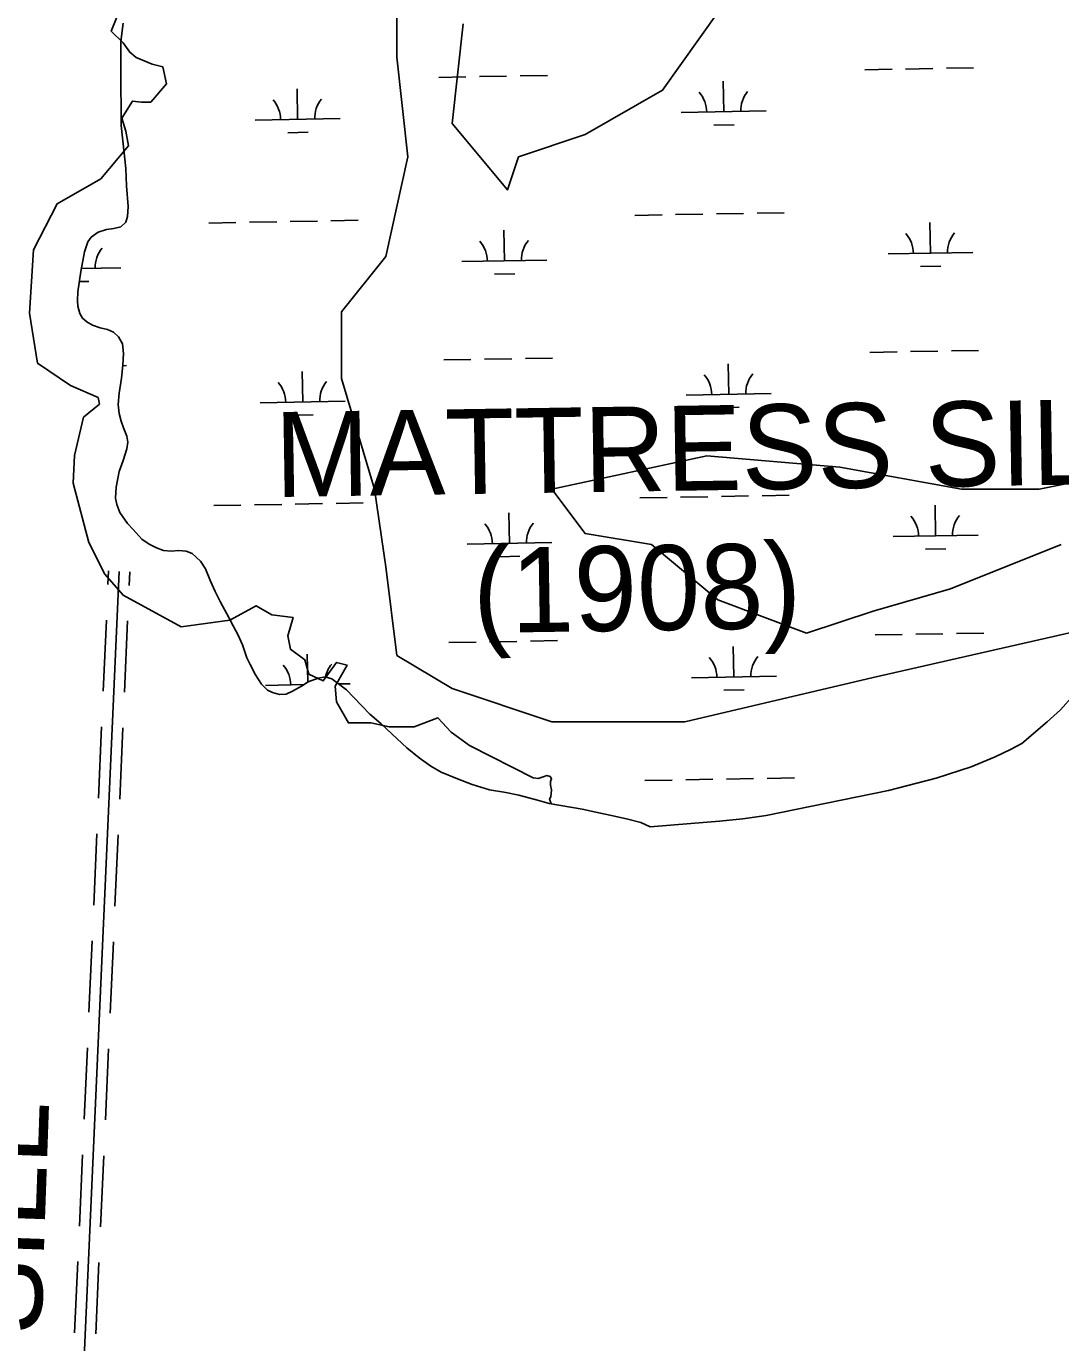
# Model space of a CAD drawing. Extents: x 3914892 to 3953151, y 242587 to 268572.
# Drawn here: x 3942954 to 3944172, y 257887 to 259437 of the extents above; entities that cross this region are included whole.
import ezdxf

# ---------------------------------------------------------------- set-up
doc = ezdxf.new("R2010")
doc.units = 0
for name, color, linetype in [('V-RIVR-EDGE', 7, 'Continuous'), ('V-RRAP-DIKE', 7, 'Continuous'), ('V-RRAP-SILL-IDEN', 7, 'Continuous'), ('V-SITE-VEGE', 7, 'Continuous'), ('V-TOPO-SHOR', 7, 'Continuous'), ('V-WETL-SWMP', 7, 'Continuous')]:
    doc.layers.add(name, color=color, linetype=linetype)

msp = doc.modelspace()

# ---------------------------------------------------------------- linework, layer by layer
at = {"layer": 'V-RIVR-EDGE'}
for points in [[(3943066.6, 259461.9), (3943054.2, 259430.8), (3943068.1, 259416.9), (3943075.9, 259406), (3943083.6, 259399.8), (3943102.3, 259392.1), (3943114.7, 259389), (3943119.3, 259368.8), (3943100.7, 259347.1), (3943089.8, 259347.1), (3943079, 259348.6), (3943066.6, 259328.5), (3943071.2, 259313), (3943074.3, 259295.9), (3943041.8, 259257.1), (3942990.6, 259227.6), (3942962.7, 259173.3), (3942958, 259098.9), (3942967.3, 259039.9), (3943006.1, 259013.6), (3943038.7, 258999.6), (3943040.2, 258991.9), (3943021.6, 258976.3), (3943010.7, 258931.4), (3943009.2, 258898.8), (3943027.8, 258829), (3943046.4, 258791.8), (3943068.1, 258766.9), (3943136.4, 258729.7), (3943193.8, 258737.5), (3943224.8, 258754.5), (3943243.4, 258743.7), (3943268.2, 258740.6), (3943262, 258718.9), (3943265.1, 258703.3), (3943282.2, 258690.9), (3943286.8, 258673.9), (3943303.9, 258666.1), (3943319.4, 258687.8), (3943331.8, 258684.7), (3943317.9, 258659.9), (3943319.4, 258641.3), (3943333.4, 258616.5), (3943359.8, 258616.5), (3943381.5, 258611.8), (3943410.9, 258611.8), (3943438.9, 258622.7), (3943454.4, 258605.6), (3943476.1, 258590.1), (3943551.7, 258551.5)], [(3943551.4, 258551.8), (3943557.1, 258551.1), (3943562.9, 258553.3), (3943567, 258554.5), (3943571, 258553.6), (3943572.8, 258550.8), (3943571.3, 258547.6), (3943571.6, 258543.3), (3943572.6, 258538), (3943572, 258529.4), (3943570.4, 258527.1), (3943572.2, 258521.5)]]:
    msp.add_lwpolyline(points, dxfattribs=at)
at = {"layer": 'V-RRAP-DIKE'}
for points in [[(3942986.1, 257058.8), (3943063.5, 258794.9)], [(3943050.3, 258779.7), (3943051, 258795.4)], [(3943075.3, 258778.5), (3943076, 258794.3)], [(3943044.7, 258653.8), (3943048.4, 258737.7)], [(3943069.7, 258652.7), (3943073.4, 258736.6)], [(3943039.1, 258527.9), (3943042.8, 258611.8)], [(3943064.1, 258526.8), (3943067.8, 258610.7)], [(3943033.5, 258402), (3943037.2, 258486)], [(3943058.4, 258400.9), (3943062.2, 258484.8)], [(3943027.8, 258276.2), (3943031.6, 258360.1)], [(3943052.8, 258275), (3943056.6, 258359)], [(3943022.2, 258150.3), (3943026, 258234.2)], [(3943047.2, 258149.2), (3943051, 258233.1)], [(3943016.6, 258024.4), (3943020.4, 258108.3)], [(3943041.6, 258023.3), (3943045.3, 258107.2)], [(3943011, 257898.5), (3943014.7, 257982.5)], [(3943036, 257897.4), (3943039.7, 257981.3)]]:
    msp.add_lwpolyline(points, dxfattribs=at)
at = {"layer": 'V-SITE-VEGE'}
for points in [[(3943390.4, 259504.7), (3943390.4, 259400.4), (3943403.4, 259283), (3943377.4, 259165.6), (3943325.2, 259100.4), (3943325.2, 259022.1), (3943364.3, 258891.7), (3943377.4, 258800.4), (3943390.4, 258696.1), (3943455.6, 258656.9), (3943573, 258617.8), (3943729.5, 258617.8), (3943951.3, 258670), (3944238.2, 258735.2)], [(3943768.6, 259452.6), (3943703.4, 259361.3), (3943612.1, 259309.1), (3943533.9, 259283), (3943520.8, 259243.9), (3943455.6, 259322.1), (3943468.7, 259439.5)], [(3944173, 258826.5), (3944042.6, 258774.3), (3943951.3, 258748.2), (3943873, 258722.1), (3943768.6, 258761.3), (3943690.4, 258826.5), (3943612.1, 258839.5), (3943573, 258891.7), (3943755.6, 258930.8), (3943912.1, 258917.8), (3944055.6, 258891.7), (3944146.9, 258891.7), (3944277.3, 258917.8)]]:
    msp.add_lwpolyline(points, dxfattribs=at)
at = {"layer": 'V-TOPO-SHOR'}
msp.add_lwpolyline([(3943688.9, 258494.4), (3943736.6, 258498), (3943770.5, 258501), (3943797.9, 258503.7), (3943825.4, 258507.7), (3943859.8, 258514.7), (3943969.3, 258537.1), (3944025.8, 258551.4), (3944066.7, 258565), (3944095.1, 258576.8), (3944113, 258585.3), (3944126.5, 258592.5), (3944156.4, 258617.7), (3944171.9, 258631.9), (3944187.3, 258649.2)], dxfattribs=at)
at = {"layer": 'V-WETL-SWMP'}
for p, q in [((3943065.5, 259418.8), (3943068, 259440.2)), ((3943065.6, 259400.8), (3943065.5, 259418.8)), ((3943065.4, 259385.7), (3943065.6, 259400.8)), ((3944037.7, 259387.1), (3944069.7, 259387.7)), ((3943065.9, 259319.9), (3943065.4, 259385.7)), ((3943439.8, 259376.4), (3943471.8, 259377)), ((3943487.8, 259377.3), (3943519.8, 259377.8)), ((3943535.8, 259378.1), (3943567.8, 259378.7)), ((3943775.5, 259336), (3943774.8, 259372)), ((3943941.7, 259385.4), (3943973.7, 259385.9)), ((3943989.7, 259386.2), (3944021.7, 259386.8)), ((3943065.5, 259369.7), (3943066, 259369.7)), ((3943273.6, 259327), (3943273, 259363)), ((3943223.7, 259326.1), (3943323.6, 259327.9)), ((3943725.5, 259335.1), (3943825.5, 259336.9)), ((3943071.2, 259269), (3943065.9, 259319.9)), ((3943261.9, 259311.3), (3943285.9, 259311.8)), ((3943763.7, 259320.3), (3943787.7, 259320.7)), ((3943072.2, 259248.8), (3943071.2, 259269)), ((3943073.9, 259224.5), (3943072.2, 259248.8)), ((3943073.2, 259212.7), (3943073.9, 259224.5)), ((3943814.8, 259216.6), (3943846.8, 259217.1)), ((3943065.5, 259200.6), (3943071.2, 259206)), ((3943071.2, 259206), (3943073.2, 259212.7)), ((3943169, 259205), (3943201, 259205.6)), ((3943217, 259205.9), (3943249, 259206.4)), ((3943264.9, 259206.7), (3943296.9, 259207.3)), ((3943312.9, 259207.6), (3943344.9, 259208.2)), ((3943670.8, 259214), (3943702.8, 259214.6)), ((3943718.8, 259214.9), (3943750.8, 259215.4)), ((3943766.8, 259215.7), (3943798.8, 259216.3)), ((3944019, 259169.5), (3944018.3, 259205.5)), ((3943026.4, 259182.9), (3943030.5, 259188.4)), ((3943030.5, 259188.4), (3943038.8, 259194.3)), ((3943038.8, 259194.3), (3943048.7, 259197.3)), ((3943048.7, 259197.3), (3943057, 259198.4)), ((3943057, 259198.4), (3943065.5, 259200.6)), ((3943517.1, 259160.5), (3943516.5, 259196.5)), ((3943018.4, 259147.9), (3943022.8, 259171.2)), ((3943022.8, 259171.2), (3943026.4, 259182.9)), ((3943969, 259168.6), (3944069, 259170.4)), ((3943467.1, 259159.6), (3943567.1, 259161.4)), ((3943014.9, 259123.9), (3943018.4, 259147.9)), ((3943019.1, 259151.6), (3943065.3, 259152.4)), ((3943505.4, 259144.9), (3943529.4, 259145.3)), ((3944007.2, 259153.8), (3944031.2, 259154.3)), ((3943014.3, 259113.8), (3943014.9, 259123.9)), ((3943016.7, 259136.1), (3943027.6, 259136.3)), ((3943014.8, 259107.3), (3943014.3, 259113.8)), ((3943017, 259098.4), (3943014.8, 259107.3)), ((3943020.4, 259092.9), (3943017, 259098.4)), ((3943025.4, 259088.6), (3943020.4, 259092.9)), ((3943032.1, 259084.9), (3943025.4, 259088.6)), ((3943041.1, 259081.5), (3943032.1, 259084.9)), ((3943049.9, 259079.5), (3943041.1, 259081.5)), ((3943056.6, 259076.4), (3943049.9, 259079.5)), ((3943062.7, 259071.1), (3943056.6, 259076.4)), ((3943067.2, 259062.6), (3943062.7, 259071.1)), ((3943068.7, 259051.4), (3943067.2, 259062.6)), ((3943067.8, 259037.5), (3943068.7, 259051.4)), ((3943947.6, 259052.7), (3943979.6, 259053.3)), ((3943995.6, 259053.6), (3944027.6, 259054.2)), ((3944043.6, 259054.5), (3944075.6, 259055)), ((3943066.3, 259022.5), (3943067.8, 259037.5)), ((3943067.8, 259037), (3943072, 259037.1)), ((3943445.8, 259043.8), (3943477.8, 259044.3)), ((3943493.8, 259044.6), (3943525.8, 259045.2)), ((3943541.8, 259045.5), (3943573.8, 259046.1)), ((3943781.4, 259003.3), (3943780.8, 259039.3)), ((3943063.3, 259004.9), (3943066.3, 259022.5)), ((3943279.6, 258994.4), (3943278.9, 259030.4)), ((3943062.4, 258991.4), (3943063.3, 259004.9)), ((3943731.4, 259002.4), (3943831.4, 259004.2)), ((3943063.5, 258980.7), (3943062.4, 258991.4)), ((3943229.6, 258993.5), (3943329.6, 258995.3)), ((3943769.7, 258987.7), (3943793.7, 258988.1)), ((3943065.7, 258971.6), (3943063.5, 258980.7)), ((3943068.7, 258964.1), (3943065.7, 258971.6)), ((3943267.9, 258978.7), (3943291.9, 258979.1)), ((3943072.5, 258954.2), (3943068.7, 258964.1)), ((3943073.5, 258947), (3943072.5, 258954.2)), ((3943068.2, 258925.6), (3943072.3, 258939)), ((3943072.3, 258939), (3943073.5, 258947)), ((3943063.6, 258912.6), (3943068.2, 258925.6)), ((3943059.9, 258893.9), (3943063.6, 258912.6)), ((3943059.1, 258881.2), (3943059.9, 258893.9)), ((3943060.6, 258873.6), (3943059.1, 258881.2)), ((3943676.7, 258881.4), (3943708.7, 258881.9)), ((3943724.7, 258882.2), (3943756.7, 258882.8)), ((3943772.7, 258883.1), (3943804.7, 258883.7)), ((3943820.7, 258884), (3943852.7, 258884.5)), ((3943064.3, 258864.3), (3943060.6, 258873.6)), ((3943073.3, 258851.5), (3943064.3, 258864.3)), ((3943174.9, 258872.4), (3943206.9, 258873)), ((3943222.9, 258873.3), (3943254.9, 258873.8)), ((3943270.9, 258874.1), (3943302.9, 258874.7)), ((3943318.9, 258875), (3943350.9, 258875.5)), ((3943523.1, 258827.9), (3943522.4, 258863.9)), ((3944024.9, 258836.9), (3944024.3, 258872.8)), ((3943079.8, 258844.2), (3943073.3, 258851.5)), ((3943090.1, 258832.9), (3943079.8, 258844.2)), ((3943098.9, 258827.1), (3943090.1, 258832.9)), ((3943974.9, 258836), (3944074.9, 258837.7)), ((3943107.4, 258822.7), (3943098.9, 258827.1)), ((3943115.8, 258819.4), (3943107.4, 258822.7)), ((3943124.6, 258818.8), (3943115.8, 258819.4)), ((3943133.9, 258819.7), (3943124.6, 258818.8)), ((3943142.4, 258818.8), (3943133.9, 258819.7)), ((3943149.3, 258816.1), (3943142.4, 258818.8)), ((3943159.2, 258807.1), (3943149.3, 258816.1)), ((3943473.1, 258827), (3943573.1, 258828.8)), ((3944013.2, 258821.2), (3944037.2, 258821.6)), ((3943165.2, 258797.9), (3943159.2, 258807.1)), ((3943511.4, 258812.2), (3943535.4, 258812.7)), ((3943171.1, 258783.3), (3943165.2, 258797.9)), ((3943176.7, 258771.2), (3943171.1, 258783.3)), ((3943182.4, 258759.5), (3943176.7, 258771.2)), ((3943192.9, 258739.7), (3943182.4, 258759.5)), ((3943197.8, 258730.8), (3943192.9, 258739.7)), ((3943203.1, 258720.8), (3943197.8, 258730.8)), ((3943208.6, 258708.3), (3943203.1, 258720.8)), ((3944001.6, 258721), (3944033.6, 258721.6)), ((3944049.6, 258721.8), (3944081.6, 258722.4)), ((3943214, 258693.2), (3943208.6, 258708.3)), ((3943451.8, 258711.1), (3943483.7, 258711.7)), ((3943499.7, 258712), (3943531.7, 258712.6)), ((3943547.7, 258712.9), (3943579.7, 258713.4)), ((3943787.4, 258670.7), (3943786.7, 258706.7)), ((3943953.6, 258720.1), (3943985.6, 258720.7)), ((3943217.7, 258685.2), (3943214, 258693.2)), ((3943285.5, 258664.5), (3943284.9, 258697.7)), ((3943224, 258673.2), (3943217.7, 258685.2)), ((3943231.2, 258662), (3943224, 258673.2)), ((3943238, 258655.3), (3943231.2, 258662)), ((3943235.6, 258660.8), (3943280.9, 258661.7)), ((3943278, 258659.9), (3943267.7, 258653.8)), ((3943286.1, 258665), (3943278, 258659.9)), ((3943297.7, 258669.3), (3943286.1, 258665)), ((3943306.2, 258670.8), (3943297.7, 258669.3)), ((3943313.9, 258668.6), (3943306.2, 258670.8)), ((3943323.5, 258661.5), (3943313.9, 258668.6)), ((3943322.3, 258662.4), (3943335.5, 258662.6)), ((3943331, 258655.5), (3943323.5, 258661.5)), ((3943737.4, 258669.8), (3943837.4, 258671.6)), ((3943244.1, 258652.3), (3943238, 258655.3)), ((3943252.3, 258650), (3943244.1, 258652.3)), ((3943260.3, 258650.5), (3943252.3, 258650)), ((3943267.7, 258653.8), (3943260.3, 258650.5)), ((3943339.9, 258646.4), (3943331, 258655.5)), ((3943358.5, 258626.8), (3943339.9, 258646.4)), ((3943775.7, 258655.1), (3943799.6, 258655.5)), ((3944187.3, 258649.2), (3944171.9, 258631.9)), ((3944171.9, 258631.9), (3944156.4, 258617.7)), ((3943372.1, 258615.4), (3943358.5, 258626.8)), ((3943390.7, 258597.8), (3943372.1, 258615.4)), ((3944156.4, 258617.7), (3944126.5, 258592.5)), ((3943402.3, 258587.2), (3943390.7, 258597.8)), ((3943416.9, 258575.4), (3943402.3, 258587.2)), ((3944113, 258585.3), (3944095.1, 258576.8)), ((3944126.5, 258592.5), (3944113, 258585.3)), ((3943430.4, 258565.5), (3943416.9, 258575.4)), ((3944095.1, 258576.8), (3944066.7, 258565)), ((3943442.5, 258558.6), (3943430.4, 258565.5)), ((3943462, 258550.6), (3943442.5, 258558.6)), ((3943479.2, 258544.2), (3943462, 258550.6)), ((3943778.7, 258550.5), (3943810.7, 258551)), ((3943826.7, 258551.3), (3943858.7, 258551.9)), ((3944025.8, 258551.4), (3943969.3, 258537.1)), ((3944066.7, 258565), (3944025.8, 258551.4)), ((3943499.7, 258538), (3943479.2, 258544.2)), ((3943518.7, 258534.7), (3943499.7, 258538)), ((3943682.7, 258548.8), (3943714.7, 258549.3)), ((3943730.7, 258549.6), (3943762.7, 258550.2)), ((3943969.3, 258537.1), (3943859.8, 258514.7)), ((3943534, 258531.5), (3943518.7, 258534.7)), ((3943556, 258525.5), (3943534, 258531.5)), ((3943569.7, 258521.9), (3943556, 258525.5)), ((3943608.9, 258515.1), (3943569.7, 258521.9)), ((3943624.9, 258511.5), (3943608.9, 258515.1)), ((3943647, 258506.7), (3943624.9, 258511.5)), ((3943662.7, 258503.1), (3943647, 258506.7)), ((3943825.4, 258507.7), (3943797.9, 258503.7)), ((3943859.8, 258514.7), (3943825.4, 258507.7)), ((3943677.8, 258499.4), (3943662.7, 258503.1)), ((3943688.9, 258494.4), (3943677.8, 258499.4)), ((3943736.6, 258498), (3943688.9, 258494.4)), ((3943770.5, 258501), (3943736.6, 258498)), ((3943797.9, 258503.7), (3943770.5, 258501))]:
    msp.add_line(p, q, dxfattribs=at)
for centre, start, end in [((3943720.2, 259335.4), 0.2532, 41.7968), ((3943830.7, 259337.4), 140.2532, 181.7968), ((3943218.4, 259326.5), 0.2532, 41.7968), ((3943328.9, 259328.4), 140.2532, 181.7968), ((3943963.7, 259169), 0.2532, 41.7968), ((3944074.2, 259170.9), 140.2532, 181.7968), ((3943070.5, 259153), 140.2532, 181.7968), ((3943461.9, 259160), 0.2532, 41.7968), ((3943572.4, 259162), 140.2532, 181.7968), ((3943224.4, 258993.8), 0.2532, 41.7968), ((3943334.8, 258995.8), 140.2532, 181.7968), ((3943726.2, 259002.8), 0.2532, 41.7968), ((3943836.6, 259004.8), 140.2532, 181.7968), ((3944080.1, 258838.3), 140.2532, 181.7968), ((3943467.8, 258827.4), 0.2532, 41.7968), ((3943578.3, 258829.3), 140.2532, 181.7968), ((3943969.7, 258836.3), 0.2532, 41.7968), ((3943732.1, 258670.2), 0.2532, 41.7968), ((3943842.6, 258672.2), 140.2532, 181.7968), ((3943230.3, 258661.2), 0.2532, 41.7968), ((3943340.8, 258663.2), 140.2532, 167.6401)]:
    msp.add_arc(centre, 35.2, start, end, dxfattribs=at)

# ---------------------------------------------------------------- texts
at = {"layer": 'V-RRAP-SILL-IDEN'}
for s, rotation, p in [('MATTRESS SILL', 0.8953, (3943247.5, 258882.4)), ('(1908)', 0.8953, (3943480.8, 258722.3)), ('SILL', 87.987, (3942971.3, 257895.2))]:
    msp.add_text(s, height=100, rotation=rotation, dxfattribs=at).set_placement(p)

doc.saveas('drawing.dxf')
